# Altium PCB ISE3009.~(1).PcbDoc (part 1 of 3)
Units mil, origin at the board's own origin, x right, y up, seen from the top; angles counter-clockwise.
Board outline 2535 x 2952.76 mil, 4 copper layers (Top Layer, L2_P1, L3_P2, Bottom Layer), stack 90 mil thick; 177 components, 107 nets, 497 pads, 221 vias.
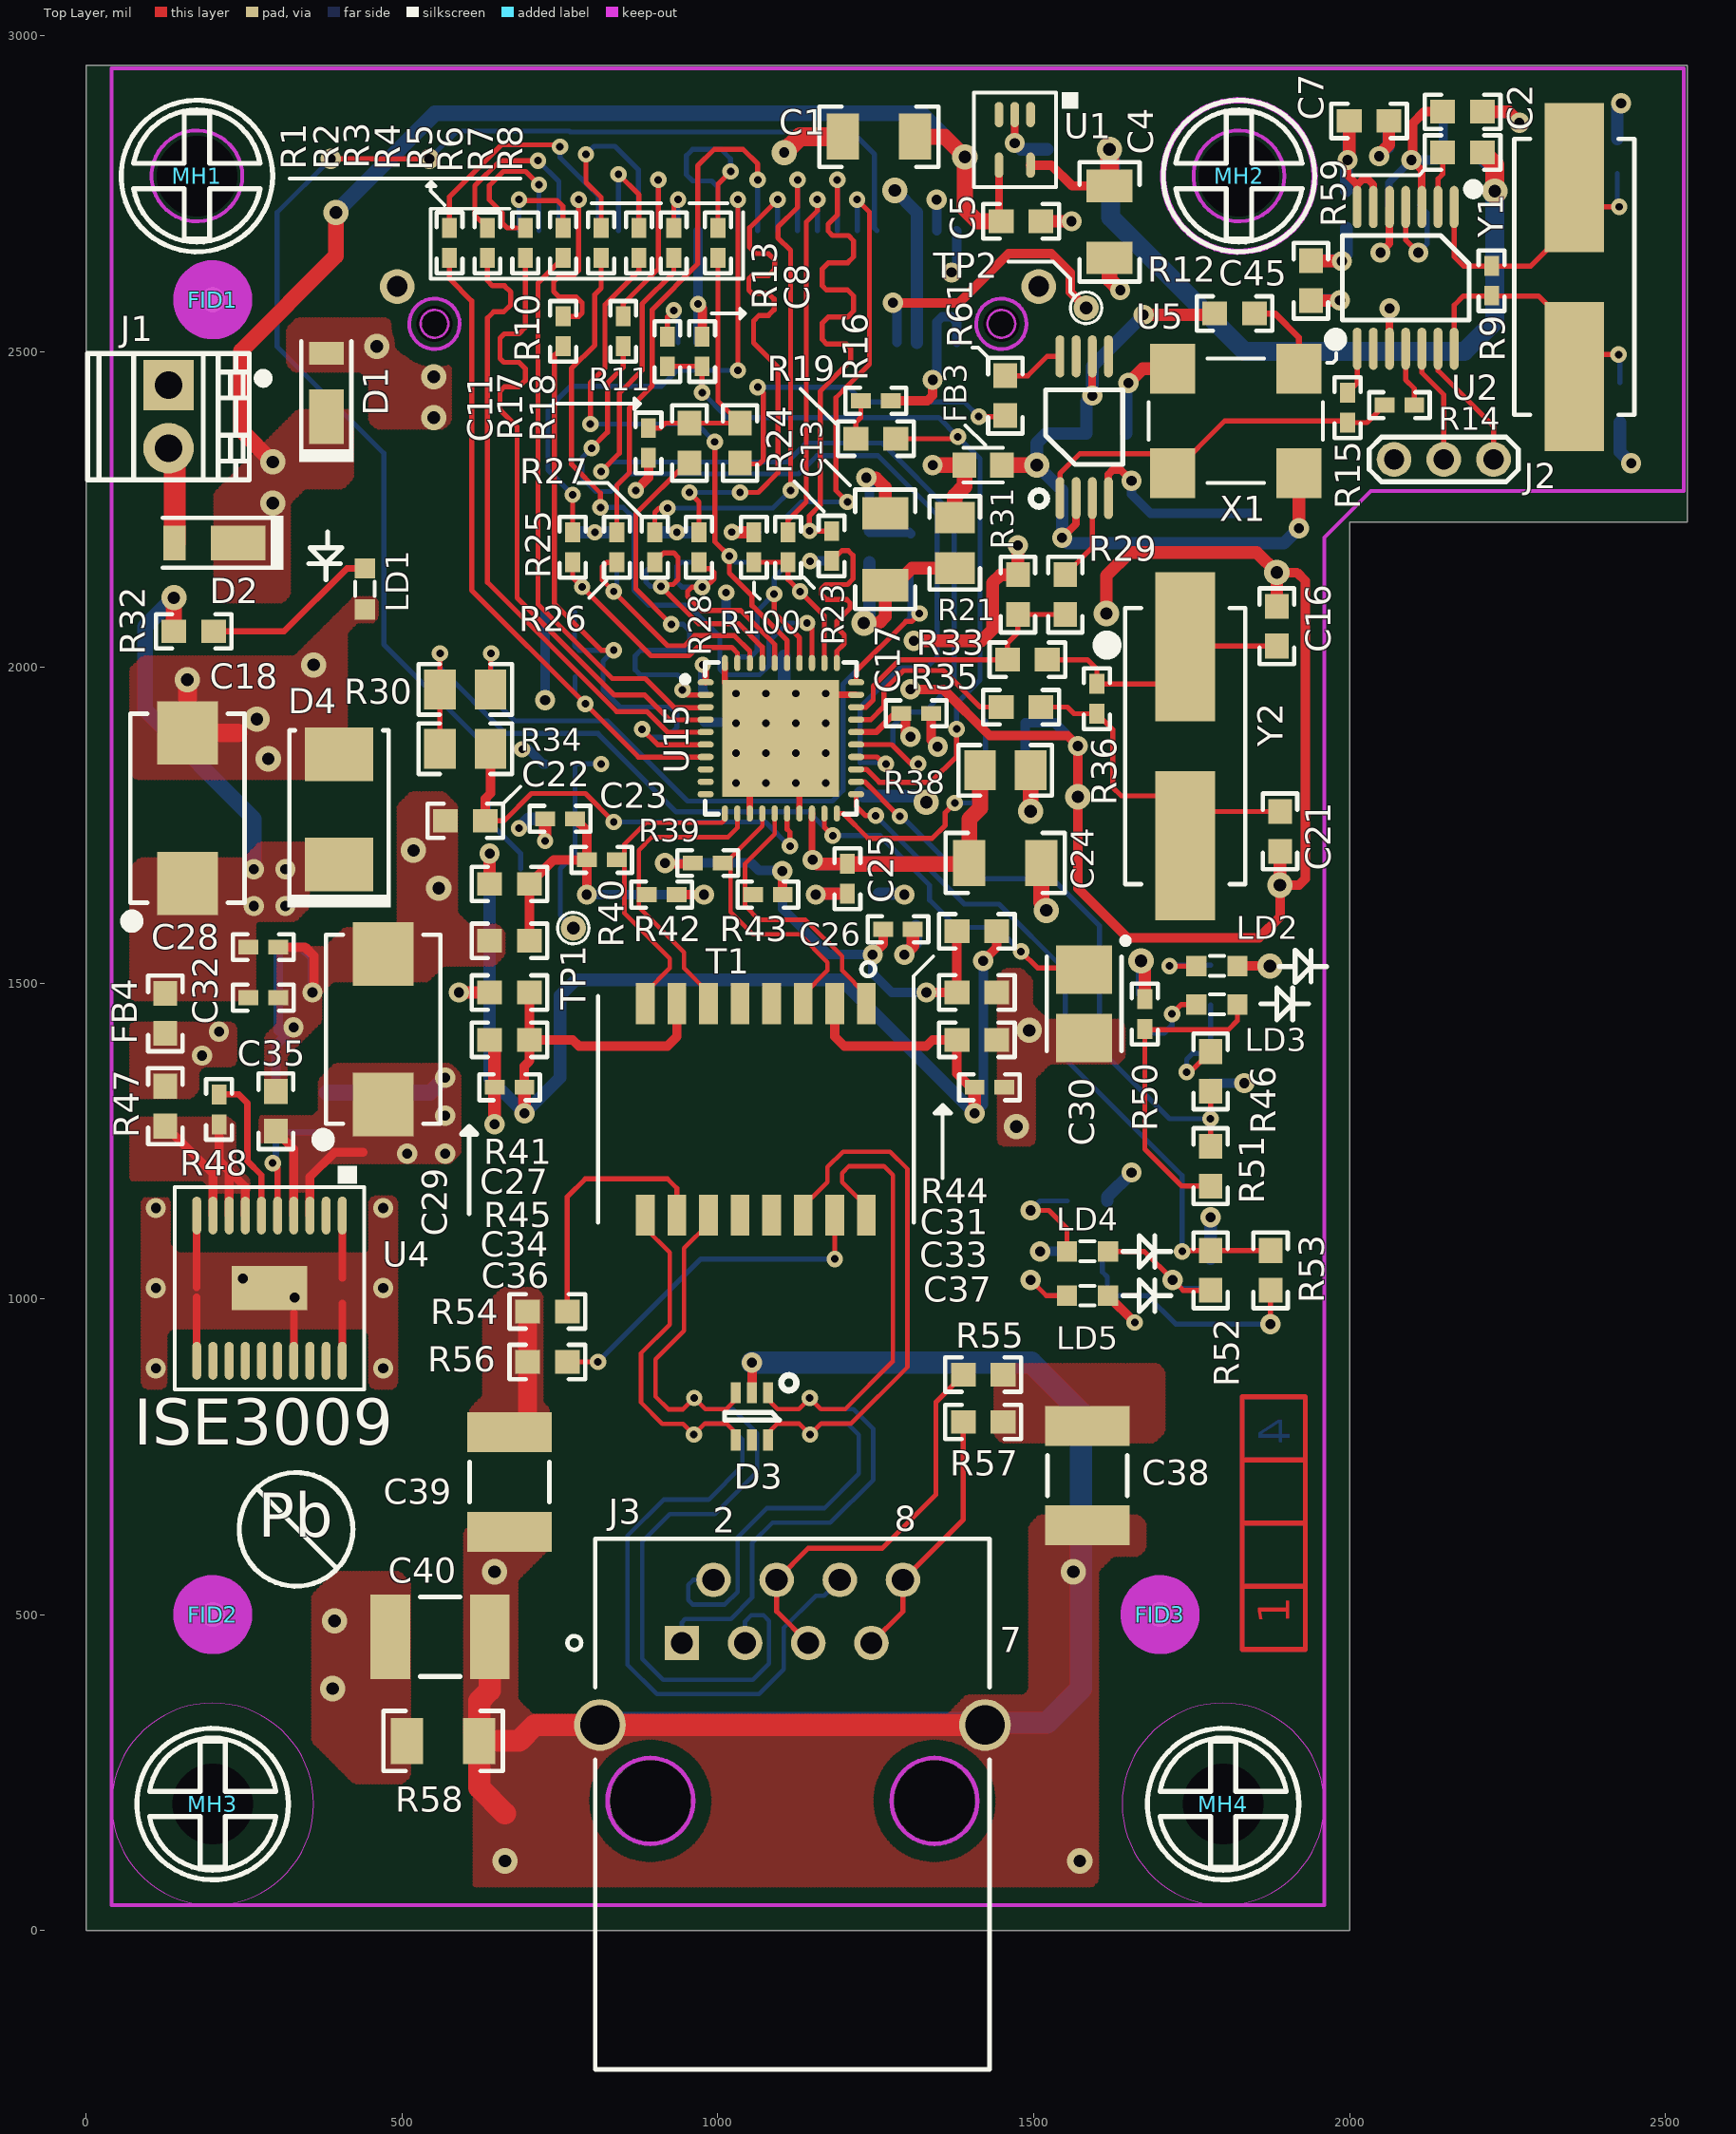
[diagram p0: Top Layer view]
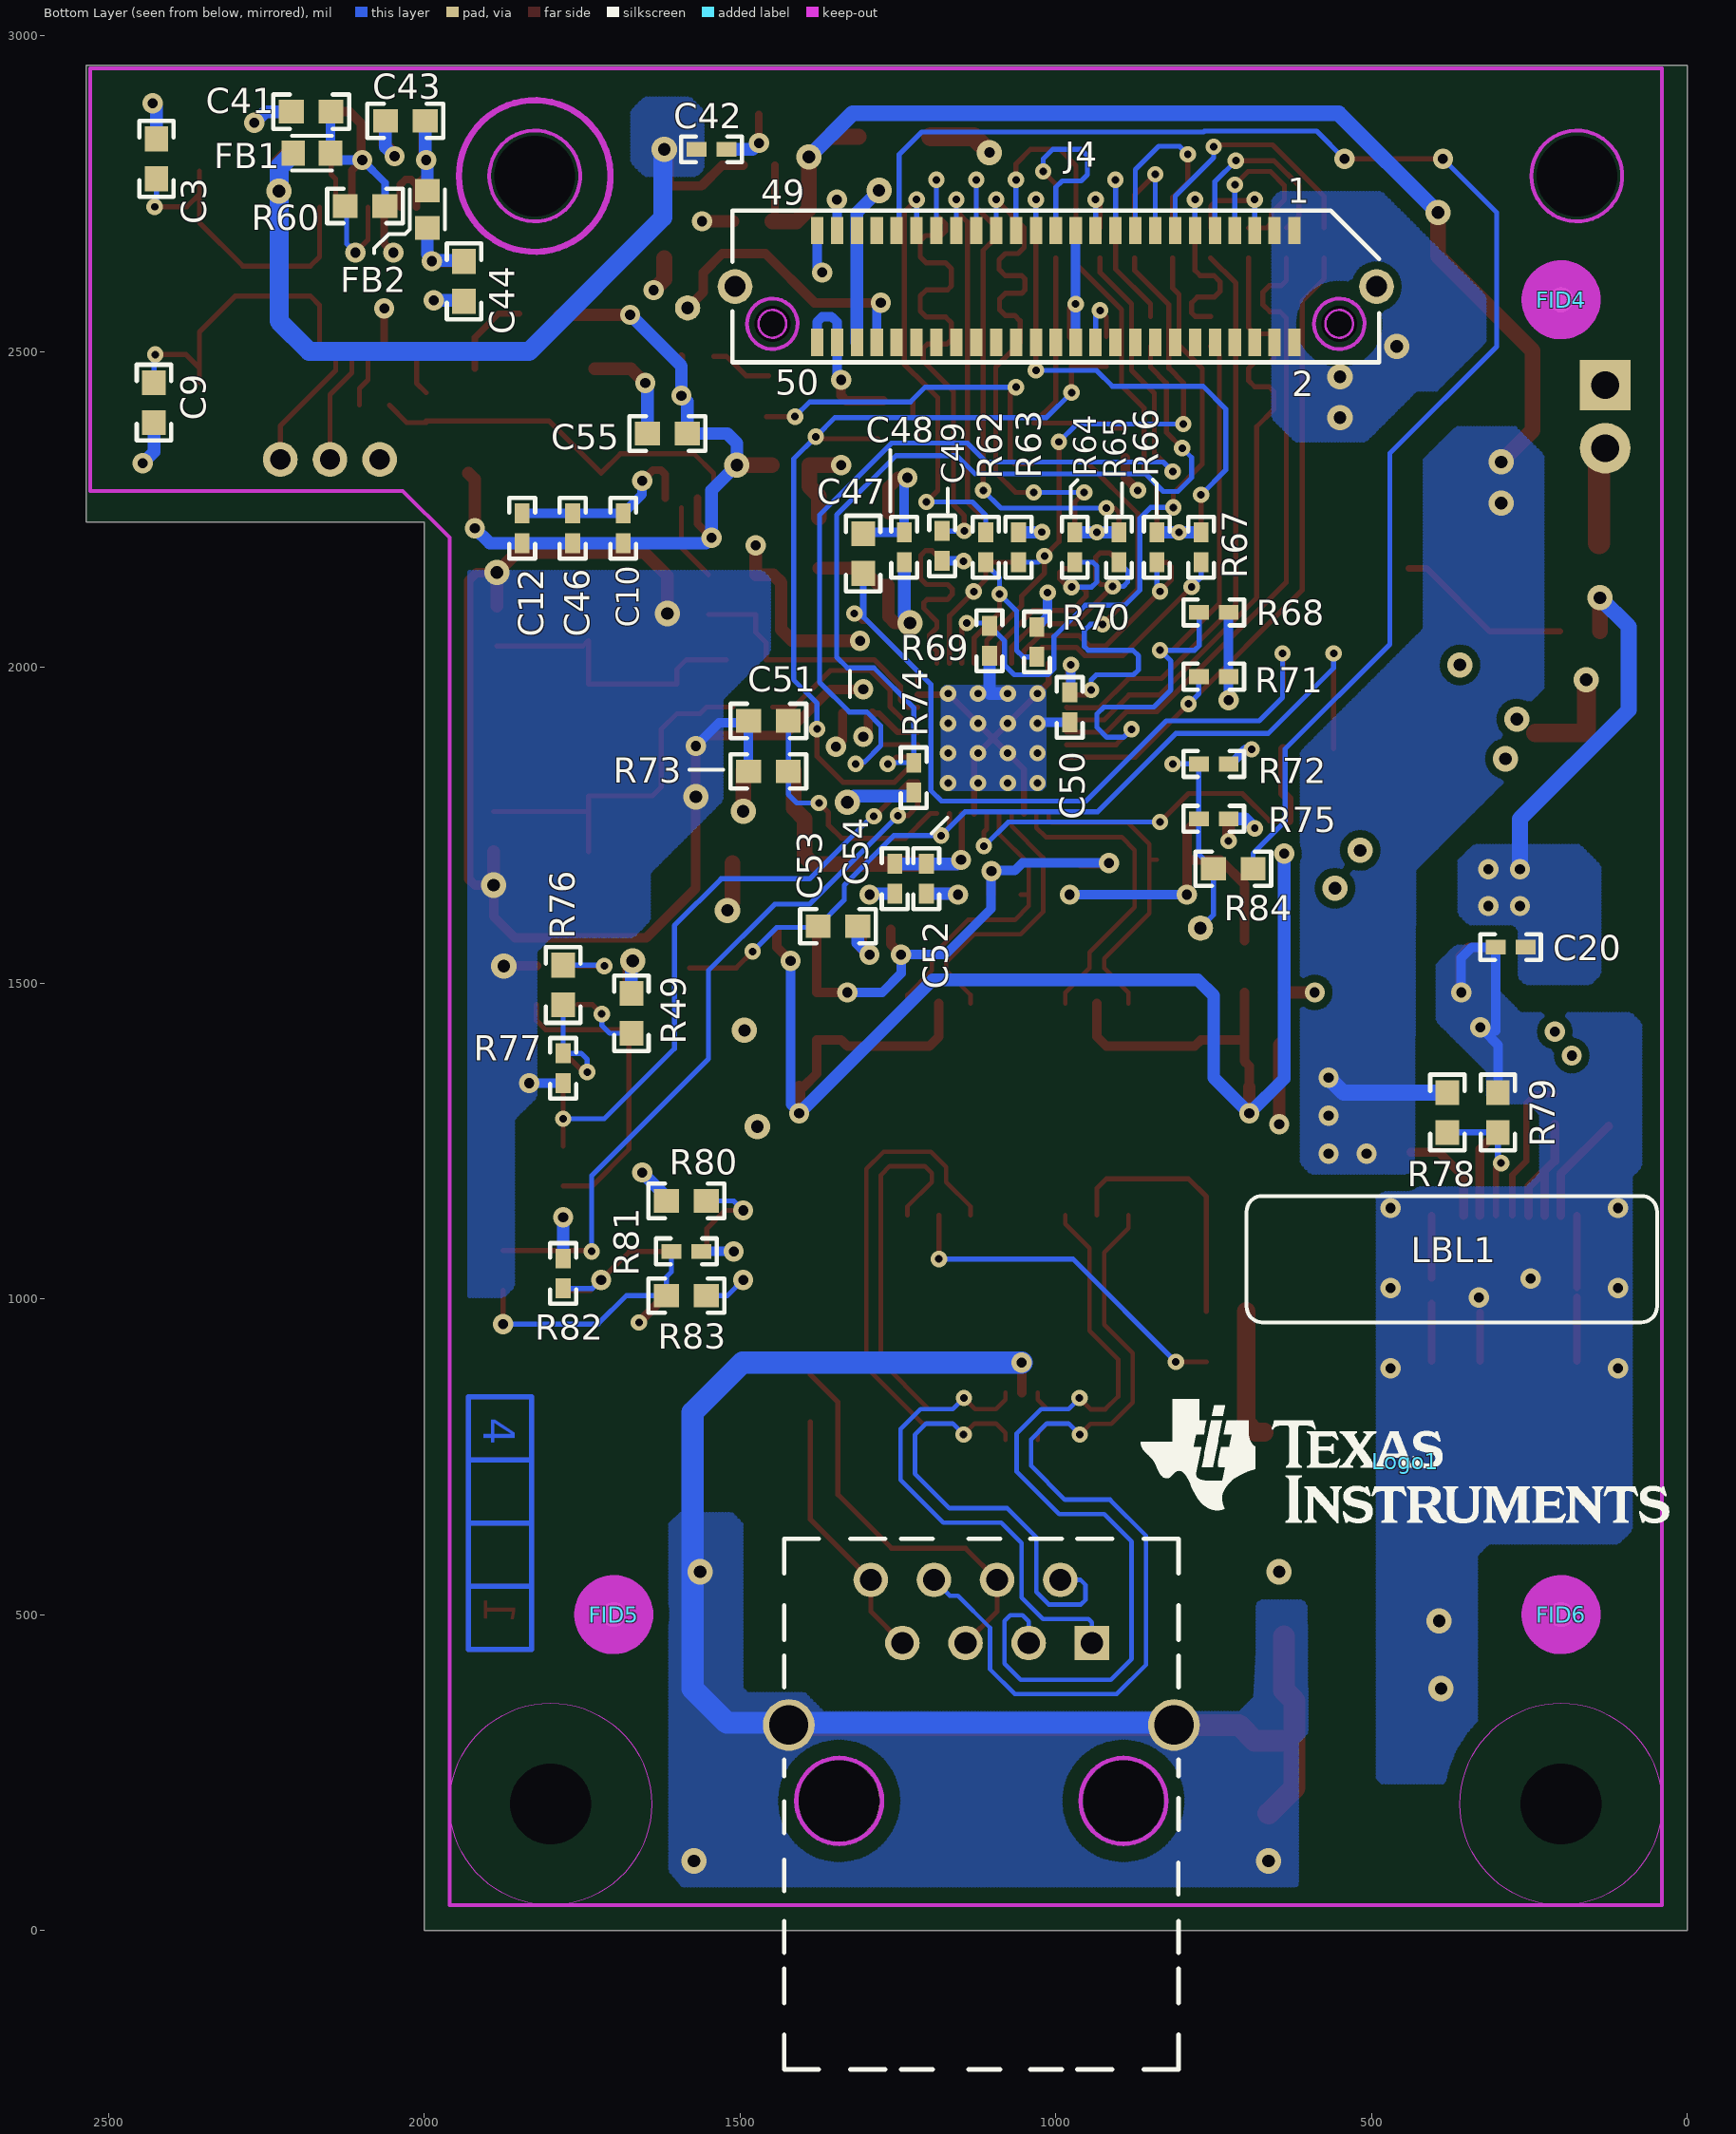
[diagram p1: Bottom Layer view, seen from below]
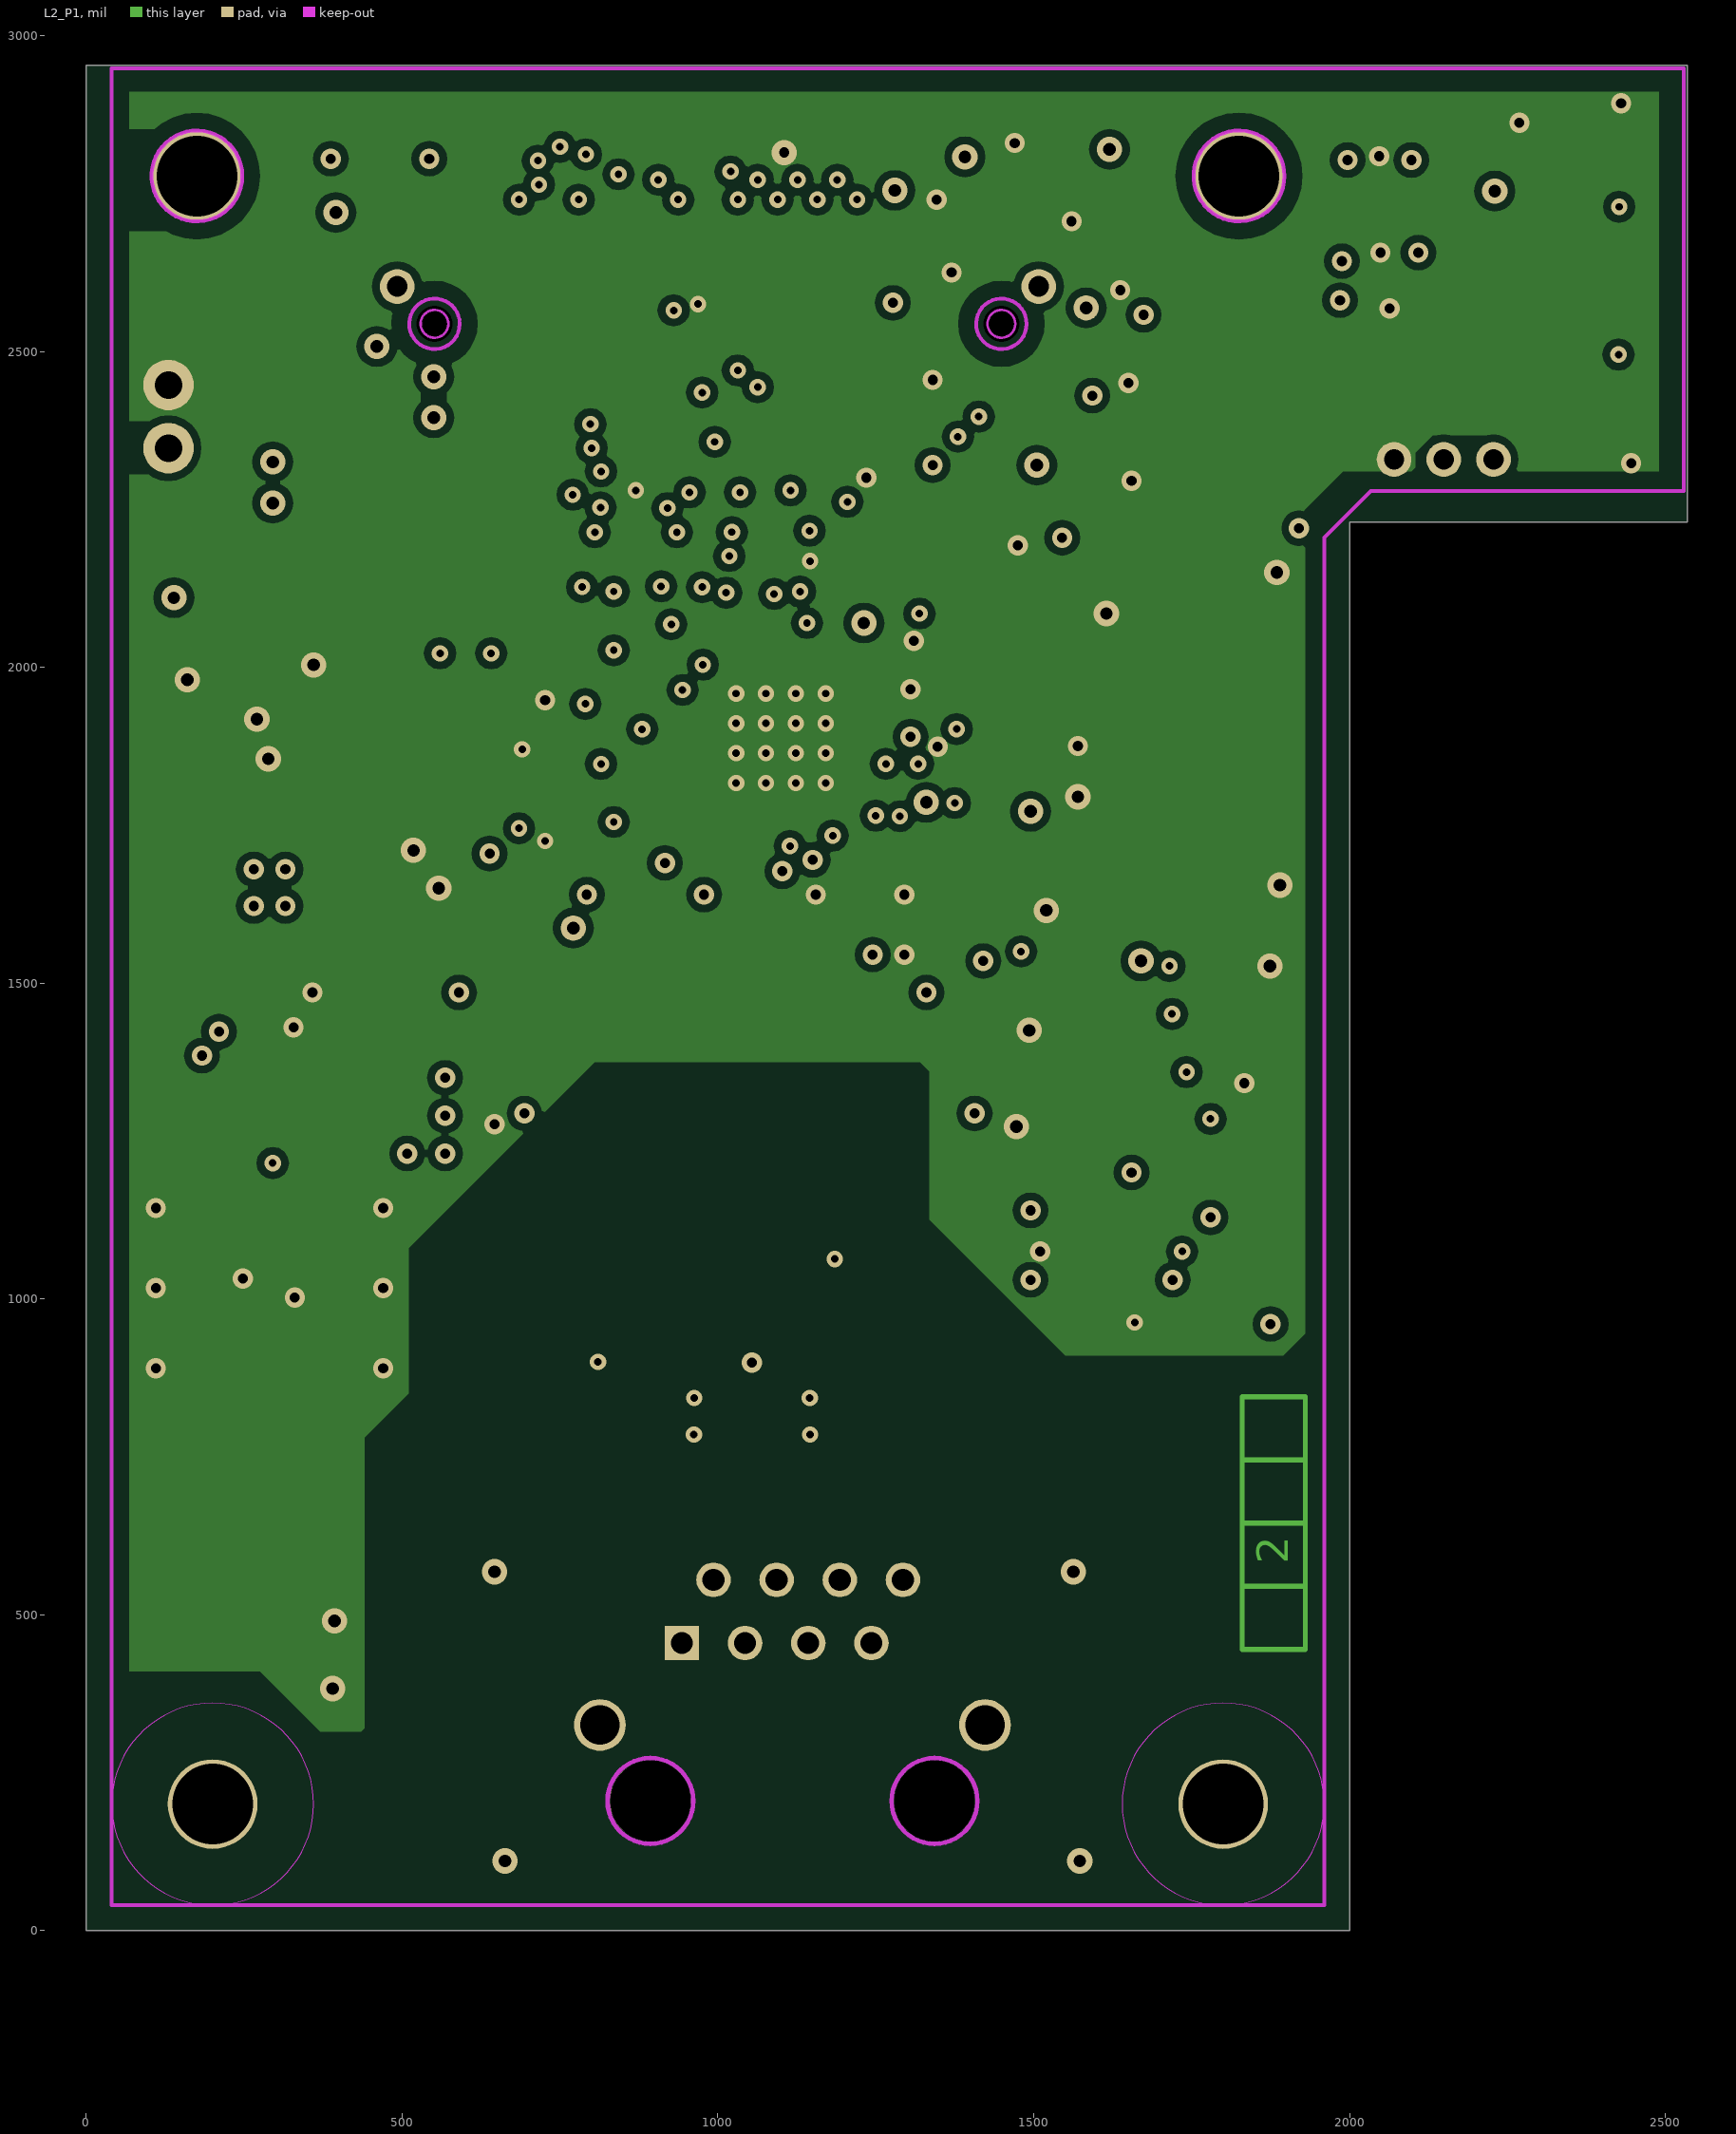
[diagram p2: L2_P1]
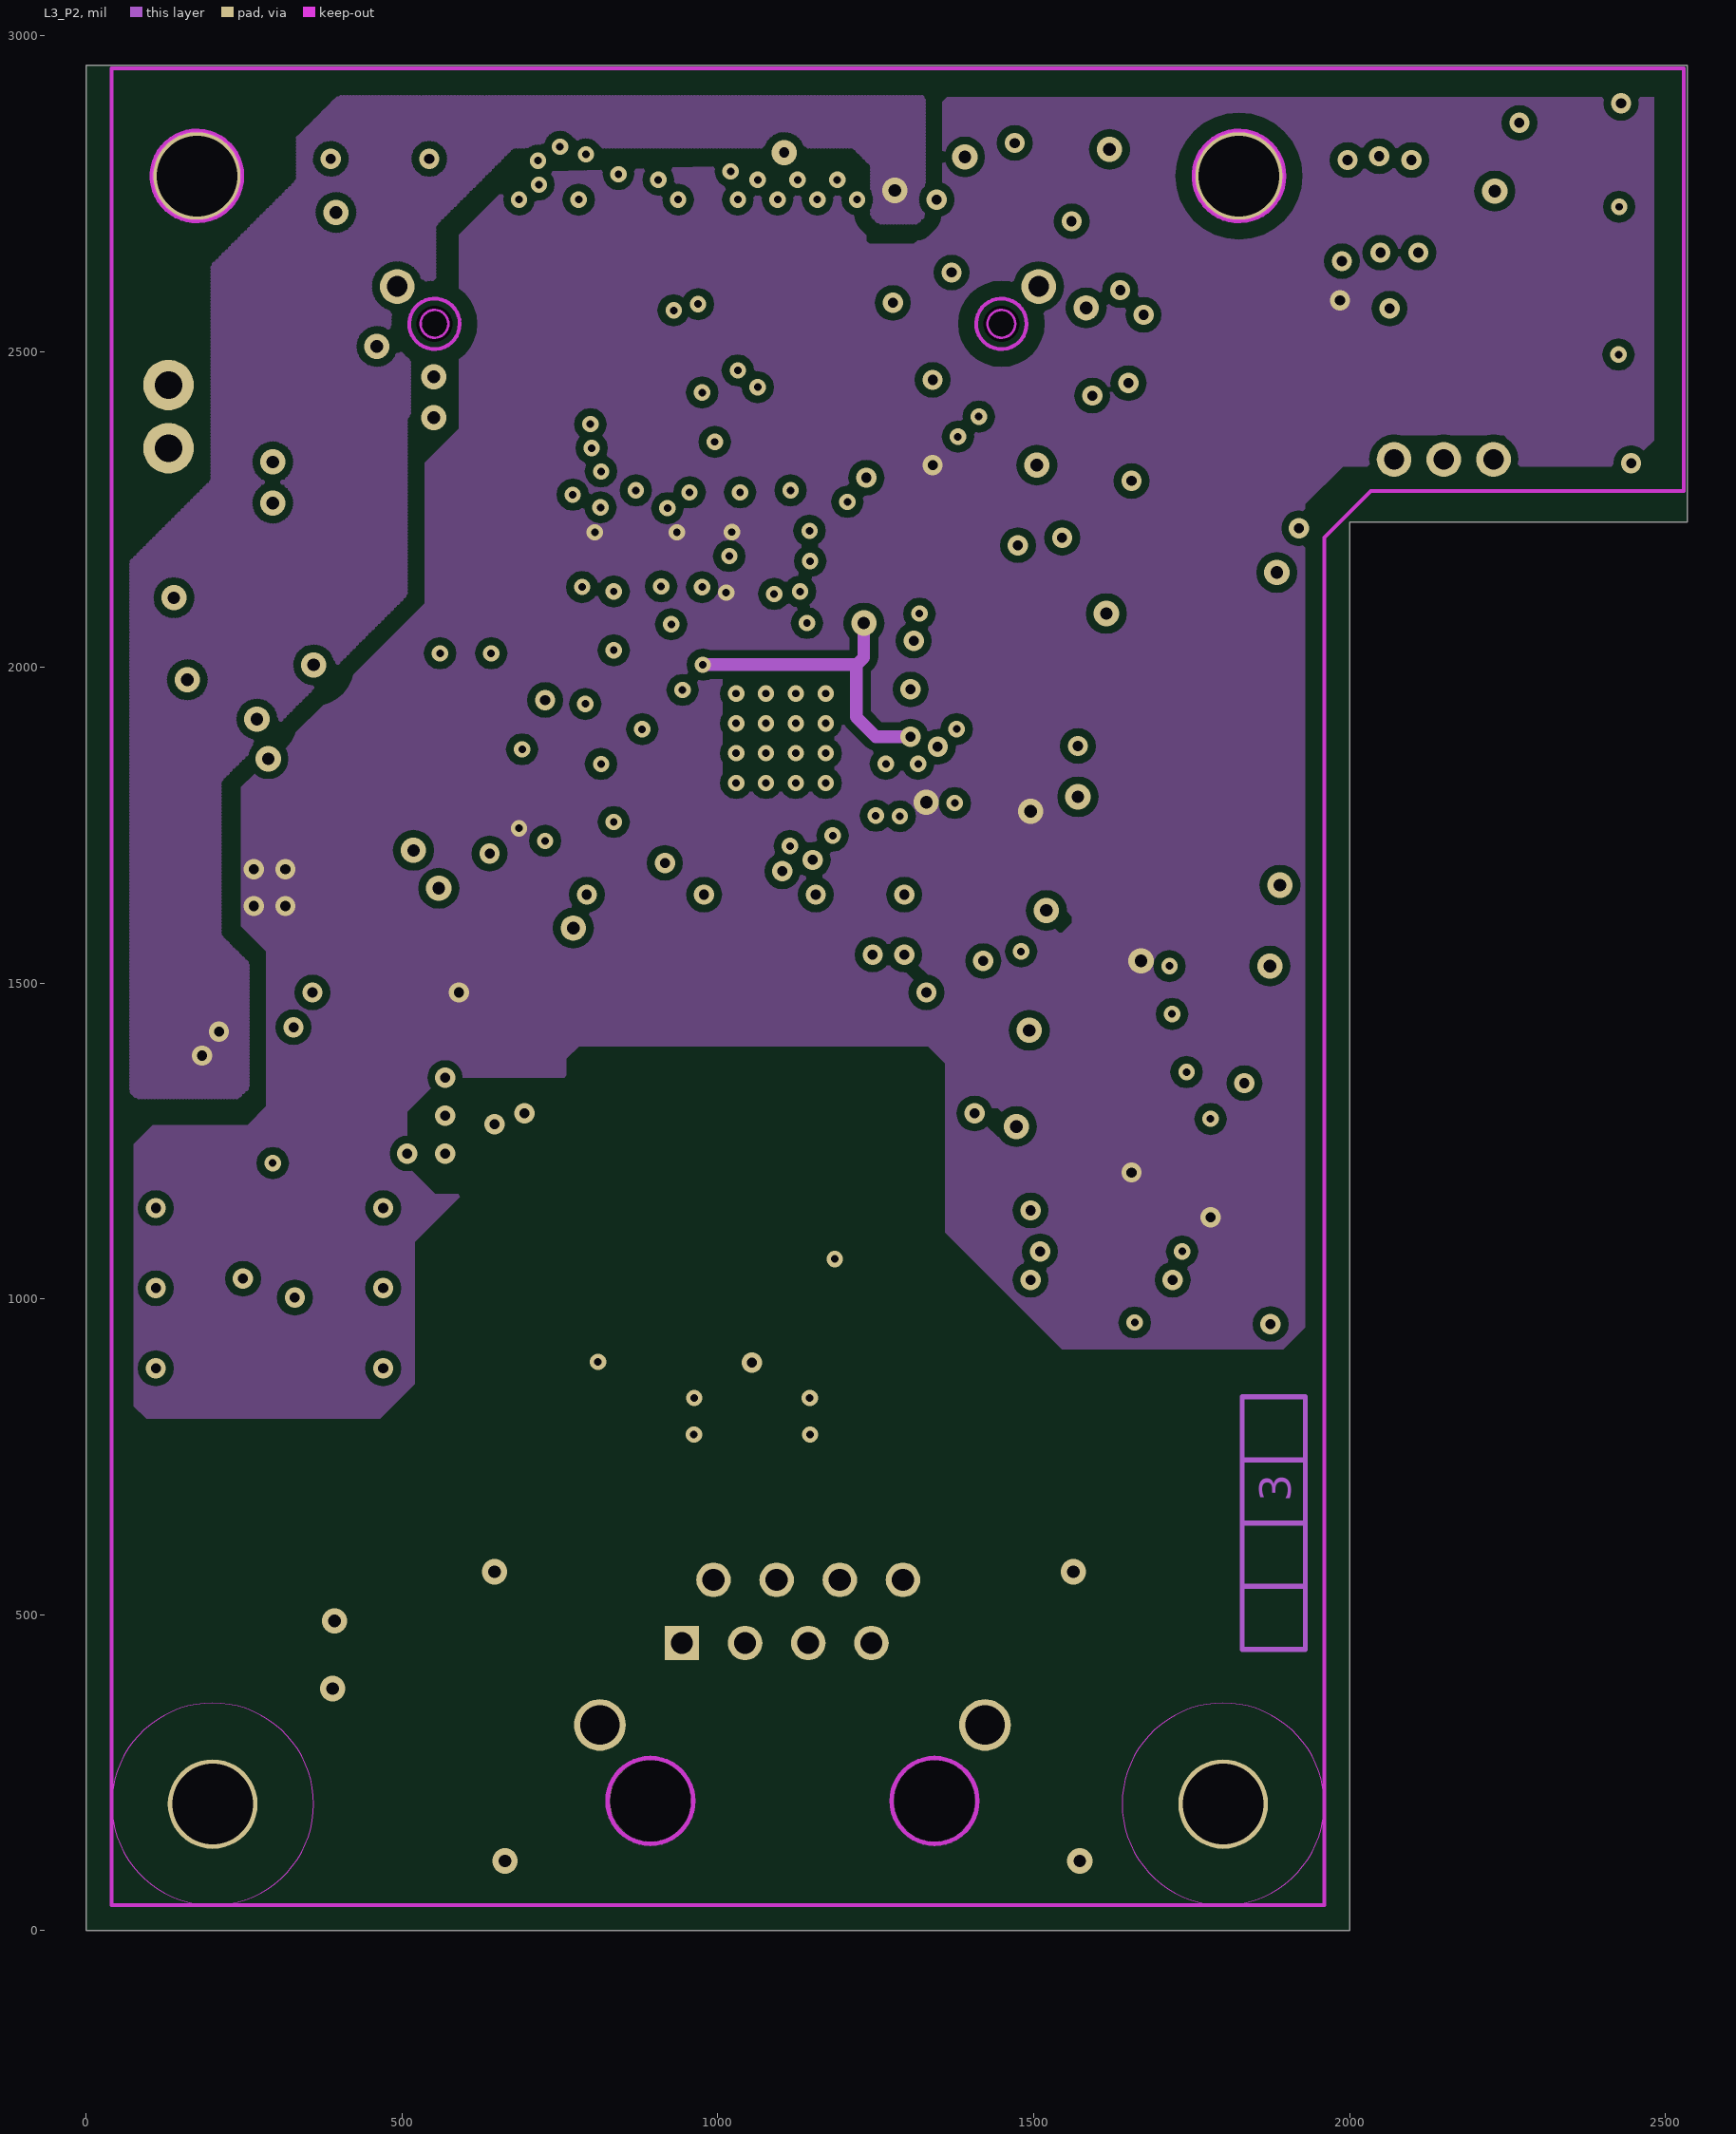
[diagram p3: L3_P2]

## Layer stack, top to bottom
Top Layer: signal copper 1.4
Dielectric: core 59.2, FR-4, Dk 4.8
L2_P1: signal copper 1.4
Dielectric: prepreg 12.6, FR-4, Dk 4.8
L3_P2: signal copper 1.4
Dielectric: core 12.6, FR-4, Dk 4.8
Bottom Layer: signal copper 1.4

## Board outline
0,0 2000,0 2000,2230 2535,2230 2535,2952.76 0,2952.76

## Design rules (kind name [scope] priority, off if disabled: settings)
AcuteAngle [All] p1: minimum=4.50000000000000E+0001 checktracksonly=FALSE
AssemblyTestPointUsage [All] p1: valid=2
Clearance "Clearance_Clk 2 Any Signals" [InNetClass('CLK_Signals') vs IsTrack] p1: gap=11
Clearance Clearance_MTG [InPadClass('MTG') vs InPolygon] p2: gap=40
Clearance Clearance_THPIN [IsVia vs IsThruPin] p3: gap=12
Clearance "Clearance_PAD Class" [InPadClass('U5') vs InPadClass('U5')] p4: gap=7.9
Clearance "Via to Via" [IsVia vs IsVia] p5: gap=12
Clearance "Via to SMT PIN" [IsVia vs IsSMTPin] p6: gap=9
Clearance "Clearance_Poly to Poly" [InPolygon vs InPolygon] p7: gap=25
Clearance Clearance_BoardEdge_Poly [OnCopper and InPoly vs IsKeepOut] p8: gap=25
Clearance Clearance_Poly [InPolygon] p9: gap=12
Clearance [All] p10: gap=8
ComponentClearance ComponentClearance_Logo [InComponentClass('Logo')] p1: gap=50 collisioncheckmode=3 verticalgap=10 showdistances=TRUE
ComponentClearance ComponentClearance_ScrewToNut [(HasFootprint('NY PMS 440 0025 PH')) vs (HasFootprint('Keystone_1902C'))] p2: gap=5 collisioncheckmode=3 verticalgap=10 showdistances=TRUE
ComponentClearance ComponentClearance_MountingHoles [InComponentClass('Mounting Holes')] p3: gap=80 collisioncheckmode=3 verticalgap=100000 showdistances=TRUE
ComponentClearance ComponentClearance_SmallPassives [HasFootprint('0201*') or HasFootprint('0402*') or HasFootprint('0508') or HasFootprint('0603*') or HasFootprint('0612') or HasFootprint('0805*') or HasFootprint('0815*') or HasFootprint('0830*') or HasFootprint('1206*') or HasFootprint('1210*') or HasFootprint('1808*') or HasFootprint('1812*') or HasFootprint('1825*') or HasFootprint('2010*') or HasFootprint('2220*') or HasFootprint('2225*') or HasFootprint('2512*') or HasFootprint('2728*') or HasFootprint('3518*') vs HasFootprint('0201*') or HasFootprint('0402*') or HasFootprint('0508') or HasFootprint('0603*') or HasFootprint('0612') or HasFootprint('0805*') or HasFootprint('0815*') or HasFootprint('0830*') or HasFootprint('1206*') or HasFootprint('1210*') or HasFootprint('1808*') or HasFootprint('1812*') or HasFootprint('1825*') or HasFootprint('2010*') or HasFootprint('2220*') or HasFootprint('2225*') or HasFootprint('2512*') or HasFootprint('2728*') or HasFootprint('3518*')] p4: gap=20 collisioncheckmode=3 verticalgap=10 showdistances=TRUE
ComponentClearance ComponentClearance_THtoSMT [IsThruComponent vs IsSMTComponent] p5: gap=40 collisioncheckmode=3 verticalgap=30 showdistances=TRUE
ComponentClearance ComponentClearance_THtoTH [IsThruComponent vs IsThruComponent] p6: gap=40 collisioncheckmode=3 verticalgap=30 showdistances=TRUE
ComponentClearance [All] p7: gap=40 collisioncheckmode=3 verticalgap=10 showdistances=TRUE
DiffPairsRouting DiffPair_TDDiffPairsRouting [InDifferentialPair ('TD')] p1: maxlimit=16 minlimit=16 mostfreqgap=16 maxuncoupledlength=500
DiffPairsRouting DiffPair_RDDiffPairsRouting [InDifferentialPair ('RD')] p2: maxlimit=16 minlimit=16 mostfreqgap=16 maxuncoupledlength=500
DiffPairsRouting "DiffPair_D3 AND D4DiffPairsRouting" [InDifferentialPair ('D3 AND D4')] p3: maxlimit=16 minlimit=16 mostfreqgap=16 maxuncoupledlength=500
DiffPairsRouting "DiffPair_D2 and D1DiffPairsRouting" [InDifferentialPair ('D2 AND D1')] p4: maxlimit=16 minlimit=16 mostfreqgap=16 maxuncoupledlength=500
DiffPairsRouting [All] p5: maxlimit=10 minlimit=10 mostfreqgap=10 maxuncoupledlength=500
FabricationTestPointUsage TestPointUsage [All] p1: valid=2 allowmultiple=FALSE
FabricationTestpoint Testpoint [All] p1: side=3 testpointundercomponent=TRUE minsize=40 maxsize=100 preferedsize=60 minholesize=0 maxholesize=40 preferedholesize=32 testpointgrid=1 allowsidetop=TRUE allowsidebottom=TRUE usegrid=TRUE gridtolerance=0.01
FanoutControl Fanout_LCC [IsLCC] p1: bgadir=Out bgaviamode=Centered fanoutstyle=Auto fanoutdirection=Alternating viagrid=1 // Fanout_LCC (Default Rule)
FanoutControl Fanout_BGA [IsBGA] p2: bgadir=Out bgaviamode=Centered fanoutstyle=Auto fanoutdirection=Alternating viagrid=1 // Fanout_BGA (Default Rule)
FanoutControl Fanout_Default [All] p4: bgadir=Out bgaviamode=Centered fanoutstyle=Auto fanoutdirection=Alternating viagrid=1 // Fanout_Default (Default Rule)
FanoutControl Fanout_Small [(CompPinCount < 5)] p5: bgadir=Out bgaviamode=Centered fanoutstyle=Auto fanoutdirection=OutThenIn viagrid=1 // Fanout_Small (Default Rule)
HoleSize [All] p1: absolutevalues=TRUE maxlimit=251 minlimit=8 maxpercent=80.000 minpercent=20.000
Length Length_RX [InNetClass('RX_1')] p1: maxlimit=900 minlimit=810
Length Length_TX [InNetClass('TX')] p2: maxlimit=1073 minlimit=1000
MatchedLengths DiffPair_TDMatchedLengths [InDifferentialPair ('TD')] p1: tolerance=1000 checknetsindiffpair=TRUE checkdiffpairvsdiffpair=TRUE checkothers=TRUE
MatchedLengths DiffPair_RDMatchedLengths [InDifferentialPair ('RD')] p2: tolerance=1000 checknetsindiffpair=TRUE checkdiffpairvsdiffpair=TRUE checkothers=TRUE
MatchedLengths "DiffPair_D3 AND D4MatchedLengths" [InDifferentialPair ('D3 AND D4')] p3: tolerance=1000 checknetsindiffpair=TRUE checkdiffpairvsdiffpair=TRUE checkothers=TRUE
MatchedLengths "DiffPair_D2 and D1MatchedLengths" [InDifferentialPair ('D2 AND D1')] p4: tolerance=1000 checknetsindiffpair=TRUE checkdiffpairvsdiffpair=TRUE checkothers=TRUE
MatchedLengths DiffPair_MatchedLengths [InDifferentialPair ('ETH1')] p5: tolerance=1000 checknetsindiffpair=TRUE checkdiffpairvsdiffpair=TRUE checkothers=TRUE
MatchedLengths DiffPair_ETH1MatchedLengths [InDifferentialPair ('ETH1')] p6: tolerance=1000 checknetsindiffpair=TRUE checkdiffpairvsdiffpair=TRUE checkothers=TRUE
MatchedLengths DiffPair_ETH1MatchedLengths_1 [InDifferentialPair ('ETH1')] p7: tolerance=1000 checknetsindiffpair=TRUE checkdiffpairvsdiffpair=TRUE checkothers=TRUE
MatchedLengths DiffPair_RS485_2MatchedLengths [InDifferentialPair ('RS485_2')] p8: tolerance=1000 checknetsindiffpair=TRUE checkdiffpairvsdiffpair=TRUE checkothers=TRUE
MatchedLengths DiffPair_RS485_1MatchedLengths [InDifferentialPair ('RS485_1')] p9: tolerance=1000 checknetsindiffpair=TRUE checkdiffpairvsdiffpair=TRUE checkothers=TRUE
MinimumAnnularRing MinimumAnnularRing_ThermalPadVias [IsVia and InAnyComponent] p1: minimumring=5.91
MinimumAnnularRing [All] p2: minimumring=7
MinimumSolderMaskSliver MinimumSolderMaskSliver_Logo [InComponentClass('Logo') vs InComponentClass('Logo')] p1: minsoldermaskwidth=0.7
MinimumSolderMaskSliver [All] p2: minsoldermaskwidth=3.94
PlaneConnect [All] p1: planeconnectstyle=Relief reliefexpansion=15 reliefentries=4 reliefconductorwidth=15 reliefairgap=12
PolygonConnect PolygonConnect_All [All] p1: connectstyle=Direct reliefconductorwidth=10 reliefentries=4 polygonreliefangle="90 Angle" airgapwidth=10
RoutingVias ThermalPadVias [IsVia and InAnyComponent] p1: holewidth=16 width=32 viastyle="Through Hole" minholewidth=12 minwidth=26 maxholewidth=20 maxwidth=40
RoutingVias [All] p2: holewidth=16 width=32 viastyle="Through Hole" minholewidth=12 minwidth=26 maxholewidth=20 maxwidth=40
SMDToCorner [All] p1: distance=30000
SilkToSilkClearance [All] p1: silktosilkclearance=5
SilkscreenOverComponentPads [All] p1: minsilkscreentomaskgap=5
SolderMaskExpansion [All] p1: expansion=2.5
Width DiffPair_TDWidth [InDifferentialPair('TD')] p1: maxlimit=7 minlimit=7 preferedwidth=7
Width DiffPair_RDWidth [InDifferentialPair('RD')] p2: maxlimit=7 minlimit=7 preferedwidth=7
Width "DiffPair_D3 AND D4Width" [InDifferentialPair('D3 AND D4')] p3: maxlimit=7 minlimit=7 preferedwidth=7
Width "DiffPair_D2 and D1Width" [InDifferentialPair('D2 AND D1')] p4: maxlimit=7 minlimit=7 preferedwidth=7
Width [All] p5: maxlimit=100 minlimit=8 preferedwidth=8 checkconnectedcopper=TRUE
14 further rules are at their usual default settings.

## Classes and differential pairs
component class Pg4: C1 C2 C3 C4 C5 C7 C9 C41 C42 C43 C44 C45 FB1 FB2 J2 R9 R14 R15 R59 R60 U1 U2 Y1
net class RX: RX_CLK RXD0 RXD1 RXD2 RXD3
component class Logo: Logo1
component class "Pg9 Hardware": FID1 FID2 FID3 FID4 FID5 FID6 LBL1 Logo1 MH1 MH2 MH3 MH4 ZZ1 ZZ2 ZZ3 ZZ4
component class FiducialMark: FID1 FID2 FID3 FID4 FID5 FID6
component class AssemblyNote: ZZ1 ZZ2 ZZ3 ZZ4
component class Label: LBL1
component class Pg3: C10 C12 C13 C16 C17 C21 C22 C24 C25 C30 C46 C47 C48 C50 C51 C52 C53 C54 C55 FB3 R12 R16 R19 R21 R29 R30 R31 R33 R34 R35 R36 R38 R61 R68 R71 R73 R74 U5 U6 U15 X1 X2 Y2
component class Pg8: C18 C20 C28 C29 C32 C35 D4 FB4 LD1 R32 R47 R48 R78 R79 U4
component class Pg5: C23 C26 C27 C31 C33 C34 C36 C37 C38 C39 C40 D3 J3 R39 R40 R41 R42 R43 R44 R45 R54 R55 R56 R57 R58 T1
component class Pg6: C8 C11 C49 D1 D2 J1 J4 R1 R2 R3 R4 R5 R6 R7 R8 R10 R11 R13 R17 R18 R23 R24 R25 R26 R27 R28 R62 TP2
component class Pg7: LD2 LD3 LD4 LD5 R46 R49 R50 R51 R52 R53 R63 R64 R65 R66 R67 R69 R70 R72 R75 R76 R77 R80 R81 R82 R83 R84 R100 TP1
net class TX: TX_CLK TX_CLK_1 TXD0 TXD1 TXD2 TXD3
net class RX_1: RX_CLK_1 RXD_0 RXD_1 RXD_2 RXD_3
net class TX_1: TX_CLK_2 TXD_0 TXD_1 TXD_2 TXD_3
net class CLK_Signals: 25M_50M_REF MDIO RX_CLK RX_CLK_1 TX_CLK TX_CLK_1 TX_CLK_2
differential pair RD: +RDP_B -RDM_B
differential pair TD: +TDP_A -TDM_A
differential pair "D3 AND D4": +RX+_RJ45 -RX-_RJ45
differential pair "D2 AND D1": +TX+_RJ45 -TX-_RJ45

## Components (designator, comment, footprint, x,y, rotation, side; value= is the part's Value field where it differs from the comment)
C1 "GRM31MR61C105KA0" 1206 1255,2840 r180 top (schematic designator C13)
C2 "C0603C224K9RACTU" 0603 2179,2879.5 r180 top (schematic designator C17)
C3 "06035A330JAT2A" 0603 2424,2805 r90 bottom (schematic designator C12)
C4 "GRM31MR61C105KA0" 1206 1620,2705 r270 top (schematic designator C22)
C5 "C0603C104Z4VACTU" 0603 1480,2706 r0 top (schematic designator C21)
C7 "C0603C224K9RACTU" 0603 2031,2865 r180 top (schematic designator C19)
C8 "C1005C0G1H150J050BA" 0402 975,2500 r90 top (schematic designator C61)
C9 "06035A330JAT2A" 0603 2428,2419 r270 bottom (schematic designator C11)
C10 "GCM155R71H103KA55D" 0402 1685,2220 r90 bottom (schematic designator C20)
C11 "GRM1555C1E390JA01D" 0402 890,2355 r270 top (schematic designator C28)
C12 "CC0402KRX7R9BB101" 0402 1845,2220 r90 bottom (schematic designator C41)
C13 "GMK316AB7106KL" 1206 1265,2186.85 r90 top (schematic designator C43)
C16 "06035A330JAT2A" 0603 1885,2065 r90 top (schematic designator C51)
C17 "CC0402KRX7R9BB101" 0402 1314,1927 r0 top (schematic designator C50)
C18 "293D107X0010D2TE3" 7343-31 160,1776.85 r90 top (schematic designator C3)
C20 "GCM155R71H103KA55D" 0402 280,1556.85 r0 bottom (schematic designator C4)
C21 "06035A330JAT2A" 0603 1890,1740 r270 top (schematic designator C48)
C22 "C0603C104K4RACTU" 0603 600,1756.85 r180 top (schematic designator C55)
C23 "C1005X5R1A104K" 0402 750,1760 r180 top (schematic designator C25)
C24 "GMK316AB7106KL" 1206 1455,1690 r0 top (schematic designator C42)
C25 "CC0402KRX7R9BB101" 0402 1205,1665 r270 top (schematic designator C49)
C26 "C1005X5R1A104K" 0402 1285,1585 r0 top (schematic designator C23)
C27 "GRM185R60J105KE26D" 0603 670,1566.85 r180 top (schematic designator C26)
C28 "GRM155R61E102KA01D" 0402 280,1556.85 r0 top (schematic designator C5)
C29 "293D107X0010D2TE3" 7343-31 470,1426.85 r90 top (schematic designator C2)
C30 "293D106X9016B2TE3" 3528-21 1580,1466.85 r270 top (schematic designator C52)
C31 "GRM185R60J105KE26D" 0603 1410,1485 r0 top (schematic designator C24)
C32 "CC0402KRX7R9BB101" 0402 280,1476.85 r0 top (schematic designator C6)
C33 "GRM185R60J105KE26D" 0603 1410,1410 r0 top (schematic designator C10)
C34 "GRM185R60J105KE26D" 0603 670,1410 r180 top (schematic designator C15)
C35 "GRM188R71C224KA01D" 0603 300,1296.85 r270 top (schematic designator C1)
C36 "C1005X5R1A104K" 0402 670,1335 r180 top (schematic designator C14)
C37 "C1005X5R1A104K" 0402 1430,1335 r0 top (schematic designator C9)
C38 "1812GC102KA1" 1812 1585,720 r270 top (schematic designator C7)
C39 "1812GC102KA1" 1812 670,710 r270 top
C40 "1812GC472KA1" 1812 560,465 r0 top (schematic designator C27)
C41 "C0603C475K9PACTU" 0603 2179,2879.5 r180 bottom (schematic designator C16)
C42 "GRM155R61E102KA01D" 0402 1545,2820 r180 bottom (schematic designator C64)
C43 "C0603C475K9PACTU" 0603 2030,2865 r180 bottom (schematic designator C18)
C44 "C0603C224K9RACTU" 0603 1937,2611 r270 bottom (schematic designator C63)
C45 "C0603C475K9PACTU" 0603 1939,2612 r270 top (schematic designator C62)
C46 "GRM155R61E102KA01D" 0402 1765,2220 r90 bottom (schematic designator C40)
C47 "C0603C104K4RACTU" 0603 1305,2180 r90 bottom (schematic designator C54)
C48 "GCM155R71H103KA55D" 0402 1240,2190 r90 bottom (schematic designator C45)
C49 "GRM1555C1E390JA01D" 0402 1180,2192 r270 bottom (schematic designator C29)
C50 "GRM155R61E102KA01D" 0402 978,1936.38 r270 bottom (schematic designator C47)
C51 "C0603C104K4RACTU" 0603 1455,1915 r180 bottom (schematic designator C56)
C52 "GRM155R61E102KA01D" 0402 1205,1665 r270 bottom (schematic designator C46)
C53 "C0603C104K4RACTU" 0603 1345,1590 r180 bottom
C54 "GCM155R71H103KA55D" 0402 1255,1665 r270 bottom (schematic designator C44)
C55 "C0603C104K4RACTU" 0603 1615,2370 r0 bottom
D1 "DFLS1200-7" powerDI123 380,2446.85 r90 top
D2 "DFLS1200-7" powerDI123 190,2196.85 r180 top
D3 "TPD4E1U06DCK" DCK0006A_N 1054,814 r270 top
D4 "1SMB5915BT3G" SMB 400,1775 r90 top
FB1 "" FB0603 2178,2814 r180 bottom
FB2 "" FB0603 1995,2725 r90 bottom
FB3 "1000 OHM" FB0603 1420,2320 r0 top (schematic designator FB4)
FB4 "CRCW06030000Z0EA" 0603 125,1451.85 r90 top (schematic designator FB3)
FID1 "Fiducial" Fiducial10-20#1 200,2581.85 r90 top locked (schematic designator FID3)
FID2 "Fiducial" Fiducial10-20#2 200,500 r90 top (schematic designator FID1)
FID3 "Fiducial" Fiducial10-20#2 1700,500 r90 top locked (schematic designator FID2)
FID4 "Fiducial" Fiducial10-30 200,2581.85 r90 bottom (schematic designator FID5)
FID5 "Fiducial" Fiducial10-30 1700,500 r90 bottom locked (schematic designator FID4)
FID6 "Fiducial" Fiducial10-30 200,500 r90 bottom locked
J1 "CON-OSTVN02A150" CN2_MTB_P100_PD80_D1.1_S5.54X6.5_STACK 130,2396.85 r270 top (schematic designator J3)
J2 "HEADER_1X3X2MM" HEADER_1X3X2MM 2228,2329 r180 top (schematic designator J4)
J3 "CONN MOD JACK-6116526-1" TE_6116526-1 1117.97,199.88 r0 top locked (schematic designator U2)
J4 "ERF8-025-05.0-L-DV-K-TR" CONN_ERF8-025-05_0-L-DV-L-TR 1000.01,2602.76 r180 bottom locked (schematic designator J1)
LBL1 "Size: 0.65\" x 0.20 \"" Label_650x200 373,1062.85 r180 bottom
LD1 "LED_LG L29K-G2J1-24-Z" LED0603AA 441,2124 r90 top
LD2 "LED_LG L29K-G2J1-24-Z" LED0603AA 1790,1526.85 r180 top (schematic designator LD5)
LD3 "LED_LG L29K-G2J1-24-Z" LED0603AA 1790,1466 r180 top (schematic designator LD4)
LD4 "LED_LG L29K-G2J1-24-Z" LED0603AA 1585,1075 r180 top (schematic designator LD2)
LD5 "LED_LG L29K-G2J1-24-Z" LED0603AA 1585,1005 r180 top (schematic designator LD3)
Logo1 "Texas Instruments" TI_Stacked_SolderMask_Small 447,742.85 r180 bottom
MH1 "MH 3.2mm" MH3.2_H5_W6_KO8_STARHEAD#1 175,2777.76 r0 top (schematic designator MH3)
MH2 "MH 3.2mm" MH3.2_H5_W6_KO8_STARHEAD#1 1825,2777.76 r0 top (schematic designator MH4)
MH3 "MH 3.2mm" MH3.2_H5_W6_KO8_STARHEAD#2 200,200 r0 top locked (schematic designator MH1)
MH4 "MH 3.2mm" MH3.2_H5_W6_KO8_STARHEAD#2 1800,200 r0 top locked (schematic designator MH2)
R1 "CRCW0402100RJNED" 0402 575,2671.85 r90 top (schematic designator R23)
R2 "CRCW0402100RJNED" 0402 635,2671.85 r90 top (schematic designator R28)
R3 "CRCW0402100RJNED" 0402 695,2671.85 r90 top (schematic designator R21)
R4 "CRCW0402100RJNED" 0402 755,2671.85 r90 top (schematic designator R18)
R5 "CRCW0402100RJNED" 0402 815,2671.85 r90 top (schematic designator R29)
R6 "CRCW0402100RJNED" 0402 875,2671.85 r90 top (schematic designator R20)
R7 "CRCW0402100RJNED" 0402 930,2671.85 r90 top (schematic designator R22)
R8 "CRCW04020000Z0ED" 0402 1000,2671.85 r90 top (schematic designator R30)
R9 "CRCW04021M00FKED" 0402 2225,2612 r90 top (schematic designator R98)
R10 "CRCW0402100RJNED" 0402 755,2531.85 r90 top (schematic designator R25)
R11 "CRCW0402100RJNED" 0402 850,2531.85 r90 top (schematic designator R24)
R12 "CRCW06030000Z0EA" 0603 1818,2560 r0 top (schematic designator R66)
R13 "CRCW040233R0JNED" 0402 920,2500 r270 top (schematic designator R108)
R14 "CRCW040222R0JNED" 0402 2079,2415 r180 top (schematic designator R101)
R15 "CRCW040222R0JNED" 0402 1997,2411 r270 top (schematic designator R102)
R16 "CRCW04022K20JNED" 0402 1250,2421.85 r0 top (schematic designator R82)
R17 "CRCW0603100RJNEA" 0603 955,2355 r90 top (schematic designator R44)
R18 "CRCW06030000Z0EA" 0603 1035,2355 r270 top (schematic designator R45)
R19 "CRCW06030000Z0EA" 0603 1250,2361.85 r0 top (schematic designator R50)
R21 "RC0805JR-070RL" 0805_HV 1375,2196.85 r270 top (schematic designator R65)
R23 "CRCW0402100RJNED" 0402 1111,2190 r90 top (schematic designator R15)
R24 "CRCW0402100RJNED" 0402 1180,2191.85 r90 top (schematic designator R31)
R25 "CRCW0402100RJNED" 0402 770,2190 r90 top (schematic designator R26)
R26 "CRCW0402100RJNED" 0402 840,2190 r90 top (schematic designator R19)
R27 "CRCW0402100RJNED" 0402 900,2190 r90 top (schematic designator R16)
R28 "CRCW0402100RJNED" 0402 970,2190 r90 top (schematic designator R17)
R29 "CRCW06030000Z0EA" 0603 1550,2115 r270 top (schematic designator R73)
R30 "RC0805JR-070RL" 0805_HV 600,1965 r0 top (schematic designator R79)
R31 "RC0603JR-074K7L" 0603 1475,2115 r270 top (schematic designator R68)
R32 "RC0603FR-07470RL" 0603 170,2056.85 r180 top (schematic designator R4)
R33 "CRCW06030000Z0EA" 0603 1490,2011.85 r0 top (schematic designator R72)
R34 "RC0805JR-070RL" 0805_HV 600,1871 r0 top (schematic designator R106)
R35 "CRCW06030000Z0EA" 0603 1480,1936.85 r0 top (schematic designator R71)
R36 "CRCW04021M00FKED" 0402 1600,1950 r90 top (schematic designator R70)
R38 "RC0805JR-070RL" 0805_HV 1455,1836.85 r180 top (schematic designator R64)
R39 "CRCW040249R9FKED" 0402 984,1690 r0 top (schematic designator R10)
R40 "CRCW040249R9FKED" 0402 816,1695 r0 top (schematic designator R12)
R41 "CRCW06030000Z0EA" 0603 670,1656.85 r0 top (schematic designator R14)
R42 "CRCW040249R9FKED" 0402 911,1640 r180 top (schematic designator R11)
R43 "CRCW040249R9FKED" 0402 1079,1640 r180 top (schematic designator R9)
R44 "CRCW06030000Z0EA" 0603 1410,1581.85 r180 top (schematic designator R13)
R45 "CRCW06030000Z0EA" 0603 670,1485 r180 top (schematic designator R43)
R46 "CRCW06030000Z0EA" 0603 1780,1360 r270 top (schematic designator R53)
R47 "CRCW06030000Z0EA" 0603 125,1305 r90 top (schematic designator R42)
R48 "CRCW04023K30JNED" 0402 210,1300 r270 top (schematic designator R3)
R49 "RC0603FR-07470RL" 0603 1672,1452 r90 bottom
R50 "CRCW04022K20JNED" 0402 1676,1451 r90 top (schematic designator R48)
R51 "CRCW06030000Z0EA" 0603 1780,1210 r270 top (schematic designator R52)
R52 "CRCW06030000Z0EA" 0603 1780,1045 r270 top (schematic designator R54)
R53 "CRCW06030000Z0EA" 0603 1875,1045 r90 top (schematic designator R55)
R54 "RC0603FR-0775RL" 0603 730,980 r0 top (schematic designator R8)
R55 "RC0603FR-0775RL" 0603 1420,880 r180 top (schematic designator R6)
R56 "RC0603FR-0775RL" 0603 730,900 r0 top (schematic designator R7)
R57 "RC0603FR-0775RL" 0603 1420,805 r180 top (schematic designator R5)
R58 "CRCW12061M00JNEA" 1206 565,300 r0 top (schematic designator R97)
R59 "RC0603JR-074K7L" 0603 2179,2815 r0 top (schematic designator R100)
R60 "RC0603JR-074K7L" 0603 2093.82,2730.15 r180 bottom (schematic designator R99)
R61 "CRCW06030000Z0EA" 0603 1455,2430 r90 top (schematic designator R107)
R62 "CRCW0402100RJNED" 0402 1111,2190 r90 bottom (schematic designator R27)
R63 "CRCW04022K20JNED" 0402 1059,2190 r90 bottom (schematic designator R36)
R64 "CRCW04022K20JNED" 0402 970,2190 r90 bottom (schematic designator R38)
R65 "CRCW04022K20JNED" 0402 900,2190 r90 bottom (schematic designator R37)
R66 "CRCW04022K20JNED" 0402 840,2190 r90 bottom (schematic designator R41)
R67 "CRCW04022K20JNED" 0402 770,2190 r90 bottom (schematic designator R40)
R68 "CRCW04022K20JNED" 0402 750,2086.85 r0 bottom (schematic designator R34)
R69 "CRCW04022K20JNED" 0402 1105,2041.85 r90 bottom (schematic designator R51)
R70 "CRCW04022K20JNED" 0402 1030,2040 r90 bottom (schematic designator R35)
R71 "CRCW04022K20JNED" 0402 750,1985 r0 bottom (schematic designator R78)
R72 "CRCW04022K20JNED" 0402 750,1846.85 r0 bottom (schematic designator R76)
R73 "CRCW06034K87FKEA" 0603 1455,1835 r180 bottom (schematic designator R96)
R74 "CRCW04022K00FKED" 0402 1225,1825 r90 bottom
R75 "CRCW04022K20JNED" 0402 750,1760 r180 bottom
R76 "RC0603FR-07470RL" 0603 1780,1496.85 r90 bottom (schematic designator R46)
R77 "CRCW04022K20JNED" 0402 1780,1365 r270 bottom (schematic designator R47)
R78 "CRCW06030000Z0EA" 0603 380,1295 r270 bottom (schematic designator R1)
R79 "CRCW06030000Z0EA" 0603 300,1295 r270 bottom (schematic designator R2)
R80 "RC0603FR-07470RL" 0603 1585,1155 r0 bottom (schematic designator R57)
R81 "CRCW04022K20JNED" 0402 1585,1075 r180 bottom (schematic designator R59)
R82 "CRCW04022K20JNED" 0402 1780,1040 r90 bottom (schematic designator R56)
R83 "RC0603FR-07470RL" 0603 1585,1005 r180 bottom (schematic designator R58)
R84 "CRCW06030000Z0EA" 0603 719,1681 r0 bottom
R100 "CRCW04022K20JNED" 0402 1057,2190 r90 top
T1 "HX1198FNL" "XFMR_ HX1198FNL" 1060,1300 r270 top locked
TP1 "TP-040_RND" TP1_PD40_D0.5_S50 771,1587 r90 top
TP2 "TP-040_RND" TP1_PD40_D0.5_S50 1583,2569 r90 top
U1 "TPS71518DCKR" SOP_5P.65MM(DCK) 1470,2835 r180 top
U2 "CDCE913PW" PW0014A_N 2089,2616.5 r270 top (schematic designator U3)
U4 "TPS75433QPWP" PWP20 290,1016.85 r180 top (schematic designator U5)
U5 "CDCLVC1102PW" PW0008A_N 1580,2380 r90 top
U15 "DP83848KSQ 10/100 PHY" QFN50P600X600X80-40N 1099.68,1887.5 r0 top
X1 "HG-2150CA 25.000M-BXC3" OSC_HG-2150CA 1820,2390 r180 top (schematic designator X2)
Y1 "XTAL-ATS250BSM-1E" XTAL_ATS250BSM-1E_1 2356,2618 r270 top (schematic designator Y2)
Y2 "XTAL-445I23D25M00000" XTAL_ATS250BSM-1E_1 1740,1875 r270 top (schematic designator Y1)
ZZ1 "This Assembly Note is for PCB labels only" AssemblyNoteLabel 860,5300.85 r0 top
ZZ2 "These assemblies are ESD sensitive, ESD precautions shall be observed." AssemblyNote 860,5190.85 r0 top
ZZ3 "These assemblies must be clean and free from flux and all contaminants. Use of no clean flux is not acceptable." AssemblyNote 860,5100.85 r0 top
ZZ4 "These assemblies must comply with workmanship standards IPC-A-610 Class 2, unless otherwise specified." AssemblyNote 860,5010.85 r0 top

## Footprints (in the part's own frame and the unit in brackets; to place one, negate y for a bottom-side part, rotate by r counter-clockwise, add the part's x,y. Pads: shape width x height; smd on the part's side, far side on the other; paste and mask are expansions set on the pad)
0402 [mm] "0402 from SM-752 data"
  rect 0.8x0.6 smd: 1(-0.6,0) 2(0.6,0)
  silkscreen extent -1.22,-0.52 1.22,0.52, body extent -0.55,-0.3 0.55,0.3, height 0.6
0603 [mm] "0603 from SM-752 data"
  rect 1x0.95 smd: 1(-0.8,0) 2(0.8,0)
  silkscreen extent -1.52,-0.69 1.52,0.69, body extent -0.87,-0.47 0.87,0.47, height 0.85
0805_HV [mil] "0805 with 30mil clearance between pads"
  rect 50x63 smd: 1(-40,0) 2(40,0)
  silkscreen extent -74,-40 74,40, body extent -43,-29 43,29, height 43
1206 [mm] "1206 from SM-752 data"
  rect 1.3x1.85 smd: 1(-1.45,0) 2(1.45,0)
  silkscreen extent -2.4,-1.21 2.4,1.21, body extent -1.7,-0.9 1.7,0.9, height 1.35
1812 [mm]
  rect 1.6x3.4 smd: 1(-2,0) 2(2,0)
  silkscreen extent -0.8,-1.6 0.8,1.6, body extent -2.4,-1.7 2.4,1.7, height 1.35
3528-21 [mm] "Medium Density IPC, based on SM-782 section 8.4"
  rect 1.95x2.25 smd: 1(-1.375,0) 2(1.375,0)
  silkscreen extent -2.66,-1.5 1.9,1.79, body extent -1.85,-1.5 1.85,1.5, height 2.1
7343-31 [mm] "Medium Density based on Kemet T495 dimensions"
  rect 2.55x2.45 smd: 1(-3.025,0) 2(3.025,0)
  silkscreen extent -4.7,-2.3 3.8,2.39, body extent -3.8,-2.3 3.8,2.3, height 3.1
AssemblyNote [mil] "Assembly Note"
AssemblyNoteLabel [mil] "Assembly Note for PCB Labels"
CN2_MTB_P100_PD80_D1.1_S5.54X6.5_STACK [mil]
  rect 80x80 / inner round 80 / far side rect 80x80 hole 44: 1(-50,0)
  round 80 hole 44: 2(50,0)
  silkscreen extent -100,-128 100,160
CONN_ERF8-025-05_0-L-DV-L-TR [mm] "Samtec 25X2 Header"
  rect 0.5x1.1 smd mask+0.064: 1(9.6,2.25) 2(9.6,-2.25) 3(8.8,2.25) 4(8.8,-2.25) 5(8,2.25) 6(8,-2.25) 7(7.2,2.25) 8(7.2,-2.25) 9(6.4,2.25) 10(6.4,-2.25) 11(5.6,2.25) 12(5.6,-2.25) 13(4.8,2.25) 14(4.8,-2.25) 15(4,2.25) 16(4,-2.25) 17(3.2,2.25) 18(3.2,-2.25) 19(2.4,2.25) 20(2.4,-2.25) 21(1.6,2.25) 22(1.6,-2.25) 23(0.8,2.25) 24(0.8,-2.25) 25(0,2.25) 26(0,-2.25) 27(-0.8,2.25) 28(-0.8,-2.25) 29(-1.6,2.25) 30(-1.6,-2.25) 31(-2.4,2.25) 32(-2.4,-2.25) 33(-3.2,2.25) 34(-3.2,-2.25) 35(-4,2.25) 36(-4,-2.25) 37(-4.8,2.25) 38(-4.8,-2.25) 39(-5.6,2.25) 40(-5.6,-2.25) 41(-6.4,2.25) 42(-6.4,-2.25) 43(-7.2,2.25) 44(-7.2,-2.25) 45(-8,2.25) 46(-8,-2.25) 47(-8.8,2.25) 48(-8.8,-2.25) 49(-9.6,2.25) 50(-9.6,-2.25)
  round 1.4 hole 0.838: MH1(12.9,0) MH2(-12.9,0)
  round 1 hole 1.45 unplated mask+0.508: MH3(11.4,-1.5) MH4(-11.4,-1.5)
  silkscreen extent -13,-3.05 13,3.05, body extent -13.03,-2.8 13.03,2.8, height 5.3
DCK0006A_N [mm] "SOT23, 6-Leads, Body 2x1.3mm, Pitch 0.65mm, Lead Span 2.1mm, IPC Medium Density"
  rect 0.85x0.4 smd: 1(-0.95,0.65) 2(-0.95,0) 3(-0.95,-0.65) 4(0.95,-0.65) 5(0.95,0) 6(0.95,0.65)
  silkscreen extent -0.15,-1.1 0.15,1.1, body extent -1.14,-1 1.14,1, height 0.94
FB0603 [mm]
  rect 0.95x1 smd: 1(-0.75,0) 2(0.75,0)
  silkscreen extent -0.8,-0.7 0.8,0.7
Fiducial10-20#1 [mm]
  round 1 smd mask+0.5: 1(0,0)
  Top Layer keep-out circle w1.678: c0,0 r0.75
Fiducial10-20#2 [mm]
  round 1 smd mask+0.508: 1(0,0)
  Top Layer keep-out circle w1.678: c0,0 r0.75
Fiducial10-30 [mm]
  round 1 smd mask+0.508: 1(0,0)
  Top Layer keep-out circle w1.678: c0,0 r0.75
HEADER_1X3X2MM [mil]
  round 55 hole 32: 1(0,0) 2(78.7,0) 3(157.44,0)
  silkscreen extent -39,-35 197,35
Label_650x200 [mil] "Thermal Transfer Label"
  round 1 on Mech14: 0(0,0)
  silkscreen extent -325,-100 325,100, body extent -326,-101 326,101, height 1
LED0603AA [mil]
  rect 32x32 smd: 1(-32.48,0) 2(32.48,0)
  silkscreen extent -11,-16 90,89
MH3.2_H5_W6_KO8_STARHEAD#1 [mil]
  round 20 / inner round 142 / far side round 20 hole 128 unplated mask+68: 1(0,0)
  silkscreen extent -120,-120 120,120
MH3.2_H5_W6_KO8_STARHEAD#2 [mil]
  round 20 / inner round 142 / far side round 20 hole 128 unplated mask+68: 1(0,0)
  Keep-Out Layer region: 160,0 147.82,61.23 113.14,113.14 61.23,147.82 0,160 0,160 -61.23,147.82 -113.14,113.14 -147.82,61.23 -160,0 -160,0 -147.82,-61.23 -113.14,-113.14 -61.23,-147.82 0,-160 0,-160 61.23,-147.82 113.14,-113.14 147.82,-61.23 160,0
  silkscreen extent -120,-120 120,120
OSC_HG-2150CA [mm]
  rect 1.8x2 smd: 1(-2.54,-2.1) 2(2.54,-2.1) 3(2.54,2.1) 4(-2.54,2.1)
  silkscreen extent -4.17,-3.43 3.5,2.5, body extent -3.5,-2.5 3.5,2.5, height 1.4
powerDI123 [mm] "Diodes Inc recommended land pattern, document number DS30628 Rev. 6-2"
  rect 2.2x1.4 smd: 1(-1.275,0)
  rect 0.9x1.4 smd: 2(1.275,0)
  silkscreen extent -3.1,-1.09 1.76,1.09, body extent -2.38,-0.97 1.52,0.96, height 1
PW0008A_N [mm] "TSOP, 8-Leads, Body 3x4.4mm, Pitch 0.65mm, IPC Medium Density"
  oval 1.7x0.35 smd: 1(-2.85,0.975) 2(-2.85,0.325) 3(-2.85,-0.325) 4(-2.85,-0.975) 5(2.85,-0.975) 6(2.85,-0.325) 7(2.85,0.325) 8(2.85,0.975)
  silkscreen extent -1.5,-1.55 1.5,1.55, body extent -3.23,-1.5 3.23,1.5, height 1.2
PW0014A_N [mm] "TSOP, 14-Leads, Body 5x4.4mm, Pitch 0.65mm, IPC Medium Density"
  oval 1.7x0.35 smd: 1(-2.85,1.95) 2(-2.85,1.3) 3(-2.85,0.65) 4(-2.85,0) 5(-2.85,-0.65) 6(-2.85,-1.3) 7(-2.85,-1.95) 8(2.85,-1.95) 9(2.85,-1.3) 10(2.85,-0.65) 11(2.85,0) 12(2.85,0.65) 13(2.85,1.3) 14(2.85,1.95)
  silkscreen extent -1.7,-2.55 1.7,2.55, body extent -3.21,-2.5 3.21,2.5, height 0.98
PWP20 [mil]
  oval 14x60 smd: 1(-115.16,-115) 2(-89.57,-115) 3(-63.98,-115) 4(-38.39,-115) 5(-12.8,-115) 6(12.8,-115) 7(38.39,-115) 8(63.98,-115) 9(89.57,-115) 10(115.16,-115) 11(115.16,115) 12(89.57,115) 13(63.98,115) 14(38.39,115) 15(12.8,115) 16(-12.8,115) 17(-38.39,115) 18(-63.98,115) 19(-89.57,115) 20(-115.16,115)
  rect 120x70 smd: 21(0,0)
  silkscreen extent -138,-193 -108,-165
QFN50P600X600X80-40N [mm] "QFN, 40-Leads, Body 6.1x6.1mm (max), Pitch 0.50mm, IPC Medium Density"
  oval 0.65x0.25 smd: 1(-3.025,2.25) 2(-3.025,1.75) 3(-3.025,1.25) 4(-3.025,0.75) 5(-3.025,0.25) 6(-3.025,-0.25) 7(-3.025,-0.75) 8(-3.025,-1.25) 9(-3.025,-1.75) 10(-3.025,-2.25) 21(3.025,-2.25) 22(3.025,-1.75) 23(3.025,-1.25) 24(3.025,-0.75) 25(3.025,-0.25) 26(3.025,0.25) 27(3.025,0.75) 28(3.025,1.25) 29(3.025,1.75) 30(3.025,2.25)
  oval 0.25x0.65 smd: 11(-2.25,-3.025) 12(-1.75,-3.025) 13(-1.25,-3.025) 14(-0.75,-3.025) 15(-0.25,-3.025) 16(0.25,-3.025) 17(0.75,-3.025) 18(1.25,-3.025) 19(1.75,-3.025) 20(2.25,-3.025) 31(2.25,3.025) 32(1.75,3.025) 33(1.25,3.025) 34(0.75,3.025) 35(0.25,3.025) 36(-0.25,3.025) 37(-0.75,3.025) 38(-1.25,3.025) 39(-1.75,3.025) 40(-2.25,3.025)
  rect 4.7x4.7 smd: 41(-0.006,0)
  silkscreen extent -3.98,-3.05 3.05,3.05, body extent -3.05,-3.05 3.05,3.05, height 0.8
SMB [mil] "Molded Diode, 2-Leads, Body 5.4x3.6mm, IPC Medium Density, based on OnSemi component dimensions"
  rect 85x107.99 smd: 1(-87.01,0) 2(87.01,0)
  silkscreen extent -155,-82 125,82, body extent -106,-71 106,71, height 91
SOP_5P.65MM(DCK) [mil]
  oval 14x40 smd mask+2: 1(-25,-40) 2(0,-40) 3(25,-40) 4(25,40) 5(-25,40)
  silkscreen extent -100,-75 -75,-50
TE_6116526-1 [mm] "CONNECTOR, MODULAR JACK SHIELDED R/A, THRU-8 PIN"
  rect 1.39x1.39 hole 0.89: 1(-4.445,6.48)
  round 1.39 hole 0.89: 2(-3.175,9.02) 3(-1.905,6.48) 4(-0.635,9.02) 5(0.635,6.48) 6(1.905,9.02) 7(3.175,6.48) 8(4.445,9.02)
  round 3.25 hole 3.25 unplated mask+0.305: MH1(5.715,0.13) MH2(-5.715,0.13)
  round 2.08 hole 1.58: SH1(7.745,3.18) SH2(-7.745,3.18)
  Keep-Out Layer circle w0.178: c-5.715,0.13 r1.727
  Keep-Out Layer circle w0.178: c5.715,0.13 r1.727
  silkscreen extent -9.05,-10.67 7.93,10.67, body extent -7.94,-10.67 7.94,10.67, height 6.75
TI_Stacked_SolderMask_Small [mil]
  silkscreen extent -418,-98 418,98
TP1_PD40_D0.5_S50 [mil]
  round 40 hole 20: 1(0,0)
  silkscreen extent -25,-25 25,25
"XFMR_ HX1198FNL" [mm] "TRANSFORMER, MODULE XFMR, 16-SOIC"
  rect 1.65x0.76 smd: 1(-4.255,4.445) 2(-4.255,3.175) 3(-4.255,1.905) 4(-4.255,0.635) 5(-4.255,-0.635) 6(-4.255,-1.905) 7(-4.255,-3.175) 8(-4.255,-4.445) 9(4.255,-4.445) 10(4.255,-3.175) 11(4.255,-1.905) 12(4.255,-0.635) 13(4.255,0.635) 14(4.255,1.905) 15(4.255,3.175) 16(4.255,4.445)
  silkscreen extent -5.92,-6.35 4.55,6.35, body extent -4.55,-6.35 4.55,6.35, height 5.99
XTAL_ATS250BSM-1E_1 [mm] "CRYSTAL, SMD-2P"
  rect 5.5x2.4 smd: 1(-4.25,0) 2(4.25,0)
  rect 2x2.4 smd: 1(-2,0) 2(2,0)
  silkscreen extent -5.55,-2.41 5.55,2.41, body extent -5.55,-2.41 5.55,2.41, height 4.3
